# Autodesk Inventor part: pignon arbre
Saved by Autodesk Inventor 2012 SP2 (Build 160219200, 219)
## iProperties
Created: 2013-04
Part Number: pignon arbre
Material: Default
Document SubType Name: Modeling
Designer: papa
Density: 1 g/cm^3
Mass: 8.60807 g
Surface Area: 36.1827 cm^2
Volume: 8.60807 cm^3
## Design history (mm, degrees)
node "pignon arbre1"
node "pignon arbre"
node "Base1"
